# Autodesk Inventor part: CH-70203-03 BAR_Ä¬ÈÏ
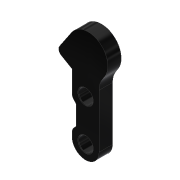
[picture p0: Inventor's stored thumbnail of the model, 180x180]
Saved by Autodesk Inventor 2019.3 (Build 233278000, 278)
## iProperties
Created: 2010-06
Part Number: CH-70203-03 BAR_Ä¬ÈÏ
Material: Ogólny
Document SubType Name: Modeling
Designer: CADENGINEERING4
Density: 1 g/cm^3
Appearance: Gładki — czarny
Author: CADENGINEERING4
Revision Number: ÈÎºÎ
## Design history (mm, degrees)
feature "NONE"
node "Bryła1"
